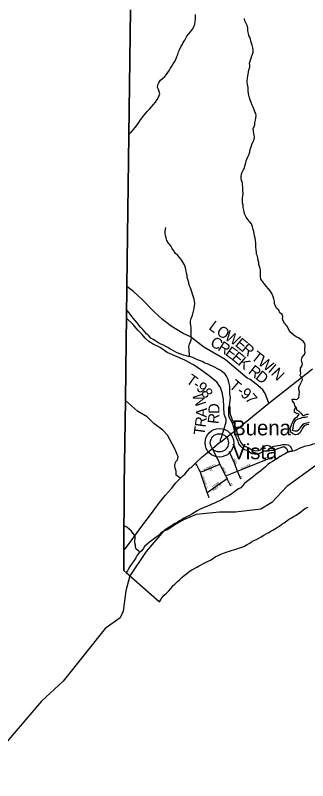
# Model space of a CAD drawing. Extents: x 1624196 to 2029251, y 146837 to 440034.
# Drawn here: x 1745980 to 1754010, y 220440 to 241485 of the extents above; entities that cross this region are included whole.
import ezdxf

# ---------------------------------------------------------------- set-up
doc = ezdxf.new("R2010")
doc.units = 0
for name, color, linetype in [('GM_X_Adjacent_County', 7, 'Continuous'), ('GM_X_County', 7, 'Continuous'), ('GM_X_Major_River', 7, 'Continuous'), ('GM_X_Minor_River', 7, 'Continuous'), ('GM_X_Township', 7, 'Continuous'), ('GM_X_Township_Road', 7, 'Continuous'), ('GM_X_Township_Road_Text', 7, 'Continuous'), ('GM_X_Township_ROW', 7, 'Continuous'), ('GM_X_Township_Subdivision', 7, 'Continuous'), ('GM_X_Township_Subdivision_Text', 7, 'Continuous'), ('GM_X_Unincorporated', 7, 'Continuous'), ('GM_X_Unincorporated_Location', 7, 'Continuous'), ('GM_X_Unincorporated_Text', 7, 'Continuous'), ('GM_X_US_Route', 7, 'Continuous')]:
    doc.layers.add(name, color=color, linetype=linetype)

msp = doc.modelspace()

# ---------------------------------------------------------------- linework, layer by layer
at = {"layer": 'GM_X_Adjacent_County'}
msp.add_lwpolyline([(1749145, 241637), (1749044, 234043), (1749032, 233161), (1749024, 232541), (1749002, 230891), (1748971, 228576), (1748962, 226751), (1748959, 226222), (1749129, 226071), (1749011, 225664), (1748943, 225098), (1748855, 224921), (1748451, 224622), (1747297, 223178), (1746699, 222628), (1744825, 220440)], dxfattribs=at)
at = {"layer": 'GM_X_County'}
msp.add_lwpolyline([(1754231, 229110), (1753434, 228531), (1753024, 228090), (1752719, 227910), (1752026, 227826), (1751591, 227819), (1750943, 227756), (1750595, 227610), (1750364, 227474), (1750158, 227337), (1750049, 227299), (1749572, 226744), (1749129, 226071), (1748959, 226222), (1748962, 226751), (1748971, 228576), (1749002, 230891), (1749024, 232541), (1749032, 233161), (1749044, 234043), (1749145, 241637)], dxfattribs=at)
at = {"layer": 'GM_X_Major_River'}
msp.add_line((1749028, 226164), (1749937, 225361), dxfattribs=at)
for points in [[(1754274, 229712), (1754153, 229689), (1754085, 229669), (1754015, 229647), (1753962, 229638), (1753912, 229628), (1753848, 229602), (1753780, 229577), (1753711, 229537), (1753647, 229506), (1753597, 229498), (1753523, 229494), (1753460, 229469), (1753394, 229429), (1753321, 229392), (1753260, 229356)], [(1753260, 229356), (1753249, 229350), (1753181, 229300), (1753120, 229265), (1753048, 229217), (1752983, 229181), (1752913, 229132), (1752852, 229070), (1752788, 229012), (1752725, 228956), (1752657, 228917), (1752590, 228859), (1752524, 228807), (1752473, 228766), (1752403, 228714), (1752330, 228656), (1752262, 228601), (1752224, 228547)], [(1752224, 228547), (1752178, 228494), (1752109, 228461), (1752043, 228419), (1751976, 228361), (1751926, 228328), (1751849, 228278), (1751780, 228241), (1751716, 228209), (1751641, 228166), (1751591, 228138), (1751525, 228107), (1751450, 228073), (1751376, 228042), (1751305, 228011), (1751235, 227981), (1751168, 227954), (1751102, 227928), (1751037, 227893), (1750971, 227857), (1750900, 227816), (1750830, 227768), (1750763, 227735), (1750699, 227705), (1750620, 227656), (1750546, 227616), (1750489, 227581), (1750429, 227539), (1750366, 227508), (1750300, 227468), (1750235, 227427), (1750167, 227387), (1750100, 227344), (1750041, 227288), (1749969, 227233), (1749902, 227173), (1749849, 227135), (1749779, 227080), (1749728, 227044), (1749664, 226995), (1749601, 226941), (1749530, 226877), (1749489, 226812), (1749437, 226754), (1749376, 226700), (1749327, 226639), (1749289, 226567), (1749244, 226493), (1749193, 226423), (1749144, 226353), (1749101, 226288), (1749058, 226214), (1749028, 226164)], [(1749937, 225361), (1749968, 225403), (1750007, 225467), (1750067, 225538), (1750132, 225594), (1750199, 225661), (1750258, 225735), (1750313, 225805), (1750363, 225843), (1750432, 225916), (1750491, 225960), (1750553, 226027), (1750618, 226081), (1750683, 226132), (1750753, 226194), (1750824, 226240), (1750897, 226277), (1750963, 226314), (1751013, 226336), (1751084, 226374), (1751152, 226411), (1751219, 226447), (1751275, 226472), (1751338, 226506), (1751404, 226551), (1751473, 226593), (1751551, 226634), (1751626, 226671), (1751727, 226707), (1751795, 226730), (1751867, 226753), (1751936, 226775), (1752010, 226796), (1752066, 226812), (1752203, 226859), (1752276, 226892), (1752348, 226936), (1752417, 226975), (1752469, 227007), (1752532, 227040), (1752602, 227068), (1752667, 227111), (1752735, 227149), (1752802, 227192), (1752872, 227232), (1752925, 227259), (1752999, 227299), (1753049, 227326), (1753126, 227374), (1753183, 227409), (1753237, 227441), (1753298, 227491), (1753364, 227532), (1753437, 227584), (1753487, 227619), (1753552, 227661), (1753624, 227704), (1753675, 227732), (1753747, 227781), (1753824, 227837), (1753887, 227884), (1753949, 227930), (1754020, 227961)]]:
    msp.add_lwpolyline(points, dxfattribs=at)
at = {"layer": 'GM_X_Minor_River'}
for points in [[(1749103, 238218), (1749158, 238272), (1749217, 238332), (1749276, 238412), (1749326, 238470), (1749369, 238542), (1749415, 238610), (1749458, 238661), (1749514, 238729), (1749565, 238795), (1749612, 238851), (1749662, 238901), (1749723, 238970), (1749763, 239028), (1749826, 239100), (1749878, 239170), (1749915, 239238), (1749948, 239324), (1749932, 239390), (1749909, 239448), (1749889, 239501), (1749891, 239571), (1749920, 239625), (1749969, 239699), (1750023, 239746), (1750090, 239804), (1750134, 239860), (1750171, 239916), (1750213, 239974), (1750244, 240036), (1750278, 240088), (1750315, 240149), (1750359, 240219), (1750400, 240299), (1750416, 240349), (1750439, 240405), (1750465, 240479), (1750488, 240537), (1750528, 240621), (1750559, 240677), (1750591, 240735), (1750634, 240801), (1750664, 240853), (1750693, 240907), (1750739, 240969), (1750794, 241028), (1750849, 241104), (1750885, 241168), (1750910, 241238), (1750918, 241316), (1750927, 241384), (1750931, 241437), (1750932, 241509)], [(1752225, 236756), (1752223, 236830), (1752217, 236882), (1752194, 236942), (1752180, 237011), (1752179, 237061), (1752191, 237115), (1752212, 237169), (1752238, 237227), (1752275, 237295), (1752297, 237371), (1752308, 237427), (1752318, 237481), (1752341, 237533), (1752373, 237609), (1752402, 237667), (1752420, 237735), (1752433, 237791), (1752455, 237867), (1752480, 237933), (1752508, 238011), (1752537, 238073), (1752551, 238139), (1752540, 238191), (1752530, 238243), (1752525, 238296), (1752515, 238362), (1752536, 238426), (1752562, 238478), (1752562, 238530), (1752573, 238600), (1752583, 238658), (1752592, 238728), (1752582, 238785), (1752561, 238835), (1752537, 238889), (1752511, 238955), (1752484, 239018), (1752456, 239086), (1752439, 239138), (1752415, 239215), (1752396, 239285), (1752386, 239337), (1752375, 239400), (1752371, 239454), (1752373, 239504), (1752358, 239582), (1752348, 239634), (1752347, 239692), (1752353, 239747), (1752370, 239817), (1752378, 239867), (1752382, 239919), (1752397, 239989), (1752424, 240059), (1752420, 240109), (1752416, 240169), (1752429, 240223), (1752445, 240279), (1752464, 240345), (1752490, 240417), (1752509, 240473), (1752515, 240541), (1752502, 240592), (1752488, 240662), (1752467, 240722), (1752451, 240773), (1752435, 240829), (1752422, 240881), (1752398, 240933), (1752384, 240988), (1752369, 241054), (1752369, 241124), (1752360, 241188), (1752316, 241261), (1752285, 241333), (1752275, 241395)], [(1753692, 230697), (1753654, 230745), (1753647, 230815), (1753593, 230871), (1753585, 230926), (1753660, 230931), (1753712, 230921), (1753766, 230977), (1753779, 231053), (1753781, 231135), (1753768, 231199), (1753768, 231251), (1753795, 231317), (1753833, 231389), (1753872, 231459), (1753854, 231517), (1753805, 231572), (1753821, 231642), (1753816, 231708), (1753814, 231786), (1753851, 231840), (1753867, 231904), (1753848, 231958), (1753836, 232013), (1753863, 232087), (1753923, 232162), (1753940, 232218), (1753934, 232273), (1753929, 232345), (1753937, 232395), (1753929, 232459), (1753882, 232528), (1753830, 232562), (1753756, 232621), (1753694, 232649), (1753625, 232694), (1753555, 232752), (1753501, 232819), (1753472, 232887), (1753436, 232944), (1753375, 233016), (1753337, 233085), (1753321, 233135), (1753324, 233203), (1753306, 233255), (1753249, 233308), (1753213, 233374), (1753157, 233435), (1753126, 233489), (1753100, 233560), (1753099, 233614), (1753079, 233692), (1753056, 233768), (1753022, 233833), (1752977, 233905), (1752921, 233974), (1752883, 234026), (1752836, 234083), (1752774, 234157), (1752727, 234228), (1752715, 234300), (1752713, 234356), (1752718, 234414), (1752714, 234465), (1752707, 234521), (1752687, 234575), (1752671, 234631), (1752664, 234687), (1752652, 234742), (1752639, 234804), (1752627, 234858), (1752608, 234922), (1752602, 234973), (1752592, 235039), (1752587, 235113), (1752589, 235163), (1752586, 235219), (1752578, 235290), (1752567, 235356), (1752551, 235420), (1752544, 235480), (1752528, 235537), (1752514, 235599), (1752493, 235673), (1752463, 235748), (1752414, 235814), (1752366, 235868), (1752319, 235937), (1752287, 236005), (1752264, 236074), (1752256, 236130), (1752240, 236196), (1752235, 236264), (1752223, 236333), (1752224, 236391), (1752222, 236459), (1752227, 236517), (1752235, 236583), (1752232, 236651), (1752228, 236706), (1752225, 236756)], [(1750765, 232097), (1750762, 232170), (1750756, 232246), (1750751, 232296), (1750749, 232367), (1750768, 232439), (1750782, 232489), (1750809, 232553), (1750817, 232625), (1750814, 232675), (1750814, 232727), (1750806, 232781), (1750809, 232833), (1750807, 232902), (1750798, 232956), (1750790, 233024), (1750793, 233076), (1750809, 233150), (1750836, 233212), (1750858, 233274), (1750873, 233348), (1750889, 233420), (1750902, 233492), (1750908, 233558), (1750903, 233627), (1750891, 233683), (1750872, 233735), (1750846, 233814), (1750831, 233878), (1750813, 233938), (1750791, 233994), (1750766, 234049), (1750748, 234127), (1750731, 234195), (1750701, 234274), (1750696, 234328), (1750680, 234398), (1750669, 234448), (1750659, 234501), (1750641, 234573), (1750622, 234627), (1750582, 234696), (1750553, 234746), (1750501, 234816), (1750441, 234877), (1750378, 234934), (1750338, 235008), (1750287, 235075), (1750247, 235143), (1750187, 235224), (1750144, 235292), (1750120, 235364), (1750109, 235433), (1750097, 235489), (1750094, 235541), (1750102, 235605), (1750113, 235655)], [(1751861, 230753), (1751868, 230825), (1751884, 230899), (1751889, 230967), (1751879, 231017), (1751870, 231082), (1751874, 231142), (1751872, 231202), (1751871, 231272), (1751861, 231324), (1751848, 231395), (1751826, 231461), (1751803, 231511), (1751777, 231562), (1751739, 231616), (1751670, 231679), (1751604, 231725), (1751534, 231768), (1751466, 231804), (1751396, 231837), (1751328, 231869), (1751259, 231898), (1751189, 231922), (1751113, 231963), (1751039, 231992), (1750987, 232016), (1750933, 232040), (1750859, 232077), (1750787, 232096), (1750733, 232100), (1750671, 232126), (1750599, 232141), (1750527, 232164), (1750471, 232182), (1750403, 232210), (1750340, 232247), (1750274, 232286), (1750220, 232318), (1750168, 232352), (1750114, 232377), (1750046, 232413), (1749974, 232446), (1749909, 232479), (1749835, 232523), (1749769, 232568), (1749705, 232610), (1749645, 232669), (1749582, 232727), (1749536, 232778), (1749478, 232844), (1749423, 232903), (1749377, 232957), (1749326, 233026), (1749272, 233090), (1749214, 233161), (1749163, 233232), (1749109, 233300), (1749056, 233373), (1749039, 233401)], [(1751859, 230755), (1751835, 230693), (1751834, 230557), (1751835, 230486), (1751849, 230424), (1751886, 230358), (1751926, 230297), (1751951, 230229), (1751965, 230179), (1751982, 230106), (1752002, 230036), (1752019, 229966), (1752039, 229891), (1752061, 229837), (1752092, 229773), (1752114, 229705), (1752167, 229638), (1752225, 229577), (1752277, 229549), (1752345, 229524), (1752409, 229484), (1752480, 229435), (1752548, 229425), (1752621, 229430), (1752673, 229440), (1752733, 229462), (1752799, 229509), (1752870, 229513), (1752944, 229514), (1753008, 229524), (1753076, 229526), (1753146, 229555), (1753215, 229583), (1753285, 229604), (1753355, 229628), (1753421, 229579), (1753459, 229517), (1753460, 229469)], [(1751869, 230725), (1751870, 230657), (1751870, 230576), (1751883, 230510), (1751907, 230444), (1751925, 230394), (1751956, 230325), (1751992, 230261), (1752011, 230192), (1752035, 230122), (1752052, 230056), (1752070, 229992), (1752095, 229921), (1752115, 229847), (1752152, 229780), (1752194, 229714), (1752240, 229660), (1752305, 229633), (1752373, 229602), (1752449, 229556), (1752521, 229525), (1752587, 229513), (1752659, 229518), (1752710, 229538), (1752762, 229582), (1752830, 229643), (1752897, 229667), (1752965, 229649), (1753019, 229608), (1753087, 229634), (1753141, 229645), (1753191, 229657), (1753259, 229669), (1753330, 229686), (1753398, 229688), (1753466, 229675), (1753530, 229639), (1753563, 229570), (1753597, 229498)], [(1754039, 230235), (1753977, 230229), (1753917, 230194), (1753864, 230130), (1753844, 230078), (1753799, 230010), (1753740, 229960), (1753672, 229951), (1753604, 229973), (1753549, 230026), (1753535, 230076), (1753531, 230126), (1753556, 230194), (1753585, 230272), (1753621, 230340), (1753670, 230410), (1753734, 230453), (1753775, 230521), (1753707, 230540), (1753647, 230574), (1753651, 230642), (1753692, 230697), (1753705, 230640), (1753771, 230600), (1753825, 230547), (1753877, 230485), (1753927, 230490), (1753985, 230516), (1754035, 230518)], [(1754053, 230285), (1753983, 230271), (1753917, 230254), (1753867, 230222), (1753810, 230162), (1753772, 230100), (1753717, 230051), (1753653, 230047), (1753595, 230069), (1753612, 230135), (1753622, 230198), (1753634, 230250), (1753647, 230300), (1753683, 230356), (1753746, 230389), (1753814, 230409), (1753884, 230436), (1753946, 230438), (1754013, 230450)], [(1753460, 229469), (1753523, 229494), (1753597, 229498)], [(1749403, 226724), (1749361, 226757), (1749299, 226805), (1749282, 226860), (1749284, 226912), (1749261, 226980), (1749259, 227042), (1749268, 227093), (1749269, 227163), (1749223, 227225), (1749164, 227306), (1749104, 227353), (1749041, 227408), (1748971, 227450), (1748969, 227451)]]:
    msp.add_lwpolyline(points, dxfattribs=at)
at = {"layer": 'GM_X_Township'}
msp.add_lwpolyline([(1754231, 229110), (1753434, 228531), (1753024, 228090), (1752719, 227910), (1752026, 227826), (1751591, 227819), (1750943, 227756), (1750595, 227610), (1750364, 227474), (1750158, 227337), (1750049, 227299), (1749572, 226744), (1749129, 226071), (1748959, 226222), (1748962, 226751), (1748971, 228576), (1749002, 230891), (1749024, 232541), (1749032, 233161), (1749044, 234043), (1749145, 241637)], dxfattribs=at)
at = {"layer": 'GM_X_Township_Road'}
for points in [[(1752943, 230817), (1752838, 231082), (1752775, 231187), (1752642, 231308), (1752591, 231347), (1752428, 231472), (1752344, 231511), (1751744, 232021), (1751157, 232363), (1750791, 232648), (1750589, 232737), (1750264, 232941), (1750020, 233121), (1749781, 233343), (1749473, 233661), (1749222, 233891), (1749044, 234032)], [(1751621, 229761), (1751618, 229804), (1751619, 229823), (1751639, 229880), (1751672, 229975), (1751705, 230088), (1751767, 230311), (1751767, 230371), (1751732, 230469), (1751713, 230519), (1751694, 230921), (1751663, 231112), (1751611, 231248), (1751524, 231387), (1751452, 231456), (1751274, 231593), (1751036, 231761), (1750853, 231883), (1750640, 231999), (1750148, 232218), (1749955, 232350), (1749767, 232446), (1749651, 232517), (1749544, 232608), (1749463, 232705), (1749346, 232827), (1749214, 232984), (1749032, 233161)]]:
    msp.add_lwpolyline(points, dxfattribs=at)
at = {"layer": 'GM_X_Township_ROW'}
msp.add_lwpolyline([(1750523, 228767), (1750468, 228790), (1750423, 228818), (1750396, 228845), (1750394, 228871), (1750394, 228950), (1750371, 229033), (1750363, 229105), (1750364, 229133), (1750370, 229152), (1750382, 229193), (1750402, 229226), (1750430, 229266), (1750443, 229298), (1750451, 229346), (1750364, 229569), (1750164, 229945), (1750029, 230082), (1749787, 230257), (1749604, 230443), (1749335, 230601), (1749171, 230744), (1749002, 230891)], dxfattribs=at)
at = {"layer": 'GM_X_Township_Subdivision'}
for points in [[(1751785, 228773), (1751784, 228774), (1751780, 228784), (1751762, 228819), (1751595, 229143), (1751577, 229195), (1751395, 229576)], [(1752172, 228727), (1752082, 228949), (1752075, 228966), (1752007, 229155), (1751881, 229440), (1751867, 229469), (1751840, 229489)], [(1751762, 228819), (1752082, 228949), (1753059, 229346)], [(1751300, 228216), (1751248, 228367), (1751072, 228886), (1751065, 228933), (1751028, 228990), (1751002, 229047), (1750968, 229118), (1750927, 229174)], [(1751065, 228933), (1751113, 228940), (1751169, 228956), (1751423, 229071), (1751515, 229106), (1751595, 229143)], [(1751898, 228535), (1751808, 228724), (1751796, 228750), (1751785, 228773)], [(1751248, 228367), (1751796, 228750)]]:
    msp.add_lwpolyline(points, dxfattribs=at)
at = {"layer": 'GM_X_Unincorporated'}
for radius in [393, 249]:
    msp.add_circle((1751585, 229730), radius, dxfattribs=at)
at = {"layer": 'GM_X_Unincorporated_Location'}
msp.add_line((1751585, 229730), (1751585, 229730), dxfattribs=at)
at = {"layer": 'GM_X_US_Route'}
for points in [[(1751610, 229753), (1751621, 229761), (1751886, 229964), (1752033, 230077), (1752498, 230451), (1752943, 230817), (1753712, 231427), (1753970, 231627), (1754145, 231763)], [(1750805, 229055), (1750927, 229174), (1751116, 229342), (1751202, 229419), (1751395, 229576), (1751610, 229753)], [(1750583, 228825), (1750642, 228882), (1750713, 228964), (1750777, 229029), (1750805, 229055)], [(1748963, 226782), (1749007, 226821), (1749233, 227135), (1749456, 227437), (1749689, 227750), (1749940, 228091), (1750108, 228291), (1750267, 228476), (1750390, 228626), (1750523, 228767), (1750583, 228825)]]:
    msp.add_lwpolyline(points, dxfattribs=at)

# ---------------------------------------------------------------- texts
at = {"layer": 'GM_X_Township_Road_Text'}
for s, rotation, p in [('L', 323.521, (1751271, 232869)), ('O', 329.7339, (1751481, 232717)), ('W', 328.7807, (1751708, 232584)), ('C', 329.306, (1751310, 232415)), ('E', 320.5223, (1751996, 232411)), ('R', 327.681, (1751520, 232290)), ('E', 324.3614, (1751724, 232161)), ('R', 319.9948, (1752169, 232268)), ('E', 320.5467, (1751902, 232034)), ('T', 321.4364, (1752435, 232045)), ('W', 324.1906, (1752623, 231896)), ('K', 320.2026, (1752075, 231891)), ('R', 321.8171, (1752357, 231658)), ('D', 322.5122, (1752554, 231504)), ('I', 318.8446, (1752899, 231697)), ('N', 314.3445, (1752987, 231620)), ('T', 324.5059, (1750649, 231399)), ('-', 324.2105, (1750832, 231269)), ('9', 322.7825, (1750930, 231198)), ('T', 319.3071, (1751833, 231268)), ('M', 108.4571, (1751230, 230801)), ('8', 305.9394, (1751061, 231103)), ('-', 328.5821, (1752046, 231090)), ('9', 323.4647, (1752145, 231030)), ('7', 310.4156, (1752280, 230932)), ('A', 88.0493, (1751238, 230422)), ('D', 91.5359, (1751588, 230530)), ('R', 83.0178, (1751556, 230238)), ('R', 82.2259, (1751202, 230145)), ('T', 82.2235, (1751171, 229923))]:
    msp.add_text(s, height=300, rotation=rotation, dxfattribs=at).set_placement(p)
at = {"layer": 'GM_X_Township_Subdivision_Text'}
for s, rotation, p in [('T', 293.3259, (1751963, 229284)), ('W', 293.3189, (1751977, 229251)), ('I', 293.3187, (1752000, 229199)), ('N', 294.8969, (1752009, 229177)), ('ST', 23.1939, (1752831, 229262)), ('M', 23.7702, (1751159, 228963)), ('A', 23.7705, (1751207, 228984)), ('N', 23.7705, (1751247, 229002)), ('S', 23.76, (1751288, 229020)), ('F', 23.7663, (1751320, 229034)), ('ST', 21.8014, (1751327, 228945)), ('I', 23.7907, (1751352, 229048)), ('E', 23.717, (1751372, 229057)), ('L', 22.4381, (1751404, 229071)), ('D', 21.3286, (1751436, 229084)), ('MAIN', 297.2549, (1751655, 229051)), ('TUCKER', 21.991, (1752180, 229003)), ('WALNUT ST', 289.1189, (1751101, 228834)), ('ST', 291.7976, (1752153, 228813)), ('STONE', 34.0451, (1751399, 228487)), ('WALL ST', 34.2154, (1751417, 228394)), ('ST', 296.5651, (1751875, 228616))]:
    msp.add_text(s, height=50, rotation=rotation, dxfattribs=at).set_placement(p)
at = {"layer": 'GM_X_Unincorporated_Text'}
for s, p in [('Buena', (1751937, 229935)), ('Vista', (1751937, 229280))]:
    msp.add_text(s, height=417, rotation=0, dxfattribs=at).set_placement(p)

doc.saveas('drawing.dxf')
